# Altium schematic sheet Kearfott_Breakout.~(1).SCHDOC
size Tabloid; Organization: Monterey Bay Aquarium Research Institute; Address1: 7700 Sandholdt Rd; Address2: Moss Landing, CA 95039-9644; CompanyName: MBARI; PageSetup: Record=PageOptions|CenterHorizontal=True|CenterVertical=True|PrintScale=0.94|XCorrection=1.00|YCorrection=1.00|PrintKind=0|BorderSize=5000000|LeftOffset=0|BottomOffset=0|Orientation=2|PaperLength=1000|PaperWidth=1000|Scale=100|PaperSource=7|PrintQuality=-4|MediaType=1|DitherType=10|PaperKind=11x17|PrintScaleMode=1
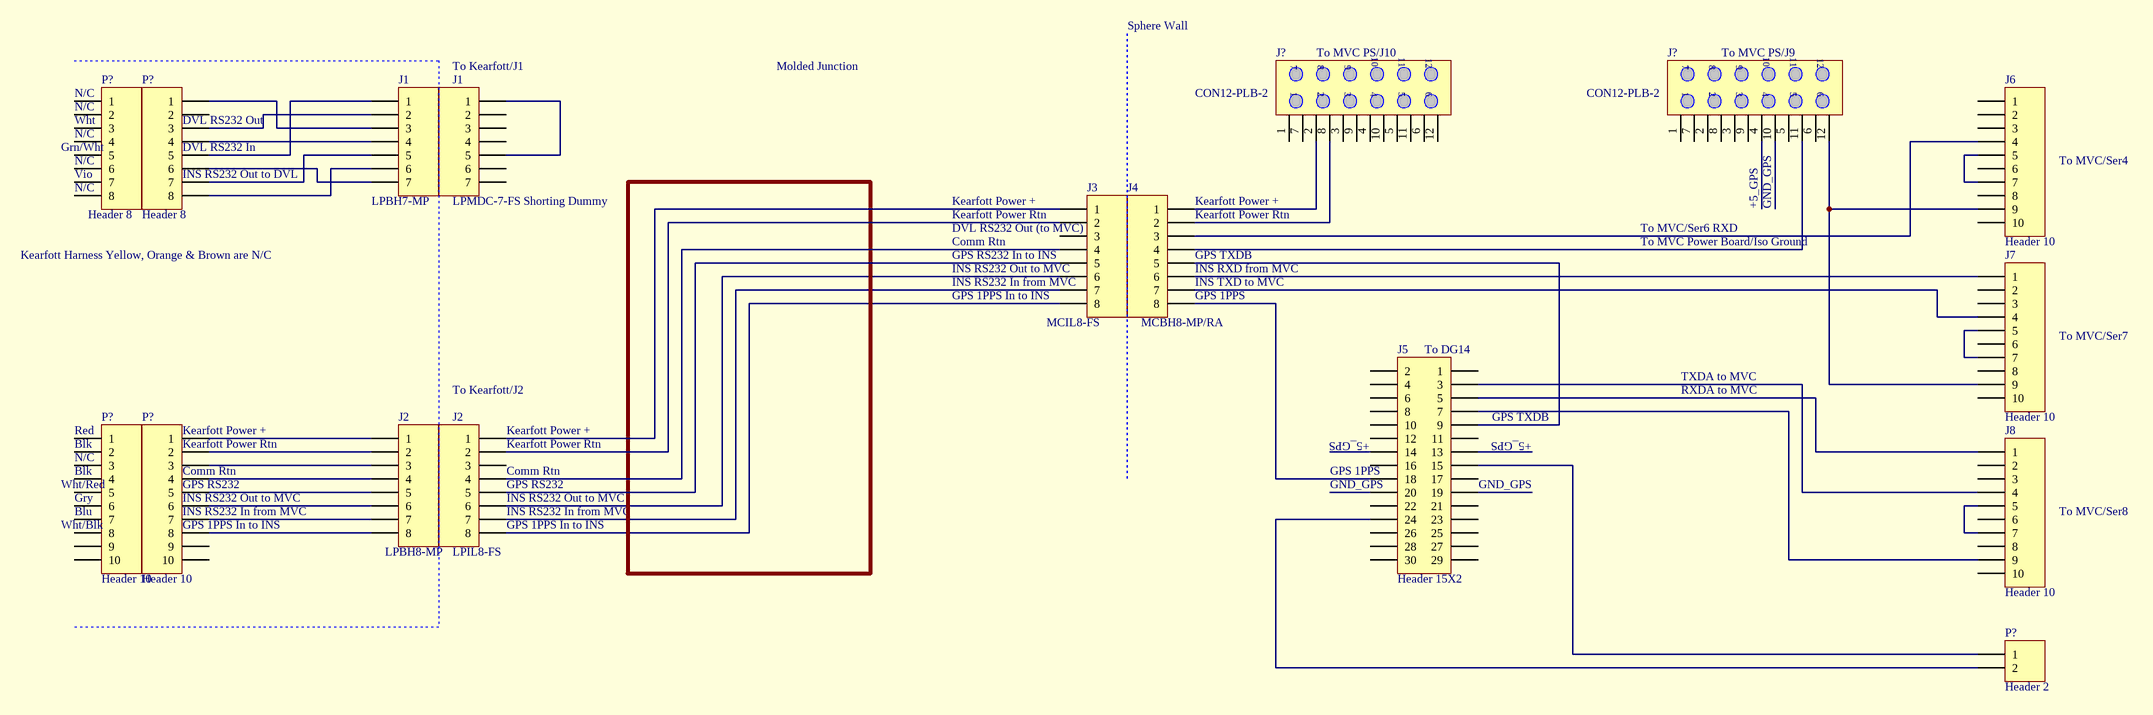
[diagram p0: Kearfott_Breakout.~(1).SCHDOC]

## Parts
(Parts that share a designator on the sheet are numbered #1, #2 ... from top to bottom, then left to right.)
J1#1  LPBH7-MP  [HDR1X7]
J1#2  LPMDC-7-FS Shorting Dummy  [HDR1X7]
J2#1  LPBH8-MP  [HDR1X8]
J2#2  LPIL8-FS  [HDR1X8]
J3  MCIL8-FS  [HDR1X8]
J4  MCBH8-MP/RA  [HDR1X8]
J5  Header 15X2  [HDR2X15]
J6  Header 10  [HDR1X10]
J7  Header 10  [HDR1X10]
J8  Header 10  [HDR1X10]
J?#1  CON12-PLB-2  [PLB12]
J?#2  CON12-PLB-2  [PLB12]
P?#1  Header 8  [HDR1X8]
P?#2  Header 8  [HDR1X8]
P?#3  Header 10  [HDR1X10]
P?#4  Header 10  [HDR1X10]
P?#5  Header 2  [HDR1X2]

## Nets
NetJ1#1_1: J1#1.1 P?#2.5
NetJ1#1_2: J1#1.2 P?#2.3
NetJ1#1_3: J1#1.3 P?#2.1
NetJ1#1_4: J1#1.4 P?#2.4
NetJ1#1_5: J1#1.5 P?#2.7
NetJ1#1_6: J1#1.6 P?#2.8
NetJ1#1_7: J1#1.7 P?#2.6
NetJ1#2_1: J1#2.1 J1#2.5
NetJ2#1_1: J2#1.1 P?#4.1
NetJ2#1_2: J2#1.2 P?#4.2
NetJ2#1_3: J2#1.3 P?#4.3
NetJ2#1_4: J2#1.4 P?#4.4
NetJ2#1_5: J2#1.5 P?#4.5
NetJ2#1_6: J2#1.6 P?#4.6
NetJ2#1_7: J2#1.7 P?#4.7
NetJ2#1_8: J2#1.8 P?#4.8
NetJ2#2_1: J2#2.1 J3.1
NetJ2#2_2: J2#2.2 J3.2
NetJ2#2_4: J2#2.4 J3.4
NetJ2#2_5: J2#2.5 J3.5
NetJ2#2_6: J2#2.6 J3.6
NetJ2#2_7: J2#2.7 J3.7
NetJ2#2_8: J2#2.8 J3.8
NetJ4_1: J4.1 J?#1.2
NetJ4_2: J4.2 J?#1.8
NetJ4_3: J4.3 J6.4
NetJ4_4: J4.4 J?#2.11
NetJ4_5: J4.5 J5.9
NetJ4_6: J4.6 J7.1
NetJ4_7: J4.7 J7.4
NetJ4_8: J4.8 J5.18
NetJ5_3: J5.3 J8.4
NetJ5_5: J5.5 J8.1
NetJ5_7: J5.7 J8.9
NetJ5_15: J5.15 P?#5.1
NetJ5_24: J5.24 P?#5.2
NetJ6_5: J6.5 J6.7
NetJ6_9: J6.9 J7.9 J?#2.12
NetJ7_5: J7.5 J7.7
NetJ8_5: J8.5 J8.7

Not connected (* = marked no-connect by the designer): J1#2 2 3 4 6 7; J2#2 3; J3 3; J5 1 2 4 6 8 10 11 12 13 14 16 17 19 20 21 22 23 25 26 27 28 29 30; J6 1 2 3 6 8 10; J7 2 3 6 8 10; J8 2 3 6 8 10; J?#1 1 3 4 5 6 7 9 10 11 12; J?#2 1 2 3 4 5 6 7 8 9 10; P?#1 1 2 3 4 5 6 7 8; P?#2 2; P?#3 1 2 3 4 5 6 7 8 9 10; P?#4 9 10

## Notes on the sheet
- Sphere Wall
- To MVC PS/J10
- To MVC PS/J9
- (near P?#1) N/C
- (near P?#1) Wht
- (near P?#2) DVL RS232 Out
- (near J1#2) To Kearfott/J1
- Molded Junction
- (near P?#1) Grn/Wht
- (near P?#1) Vio
- (near P?#2) DVL RS232 In
- (near P?#2) INS RS232 Out to DVL
- To MVC/Ser4
- Kearfott Harness Yellow, Orange & Brown are N/C
- (near J3) DVL RS232 Out (to MVC)
- (near J3) Kearfott Power +
- (near J3) Kearfott Power Rtn
- Comm Rtn
- (near J3) GPS RS232 In to INS
- (near J4) GPS TXDB
- (near J4) Kearfott Power Rtn
- (near J4) Kearfott Power +
- To MVC Power Board/Iso Ground
- To MVC/Ser6 RXD
- +5_GPS
- (near J?#2) GND_GPS
- (near J3) INS RS232 Out to MVC
- (near J3) INS RS232 In from MVC
- (near J3) GPS 1PPS In to INS
- (near J4) GPS 1PPS
- (near J4) INS TXD to MVC
- (near J4) INS RXD from MVC
- (near J2#2) To Kearfott/J2
- (near J5) To DG14
- TXDA to MVC
- RXDA to MVC
- To MVC/Ser7
- (near P?#3) Red
- (near P?#3) Blk
- (near P?#3) N/C
- (near P?#4) Kearfott Power +
- (near P?#4) Kearfott Power Rtn
- (near J2#2) Kearfott Power Rtn
- (near J2#2) Kearfott Power +
- (near J5) +5_GPS
- (near J5) GPS TXDB
- (near P?#3) Wht/Red
- (near P?#3) Wht/Blk
- (near P?#3) Gry
- (near P?#3) Blu
- (near P?#4) Comm Rtn
- (near P?#4) INS RS232 Out to MVC
- (near P?#4) INS RS232 In from MVC
- (near P?#4) GPS 1PPS In to INS
- (near P?#4) GPS RS232
- (near J2#2) GPS RS232
- (near J2#2) INS RS232 Out to MVC
- (near J2#2) INS RS232 In from MVC
- (near J2#2) GPS 1PPS In to INS
- (near J2#2) Comm Rtn
- (near J5) GPS 1PPS
- (near J5) GND_GPS
- To MVC/Ser8

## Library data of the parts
J1#1 J1#2 = Header 7: Header, 7-Pin
J2#1 J2#2 J3 J4 P?#1 P?#2 = Header 8: Header, 8-Pin
J5 = Header 15X2: Header, 15-Pin, Dual row
J6-J8 P?#3 P?#4 = Header 10: Header, 10-Pin
J?#1 J?#2 = CON12-PLB-2: Positronic 12 pin connector
P?#5 = Header 2: Header, 2-Pin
